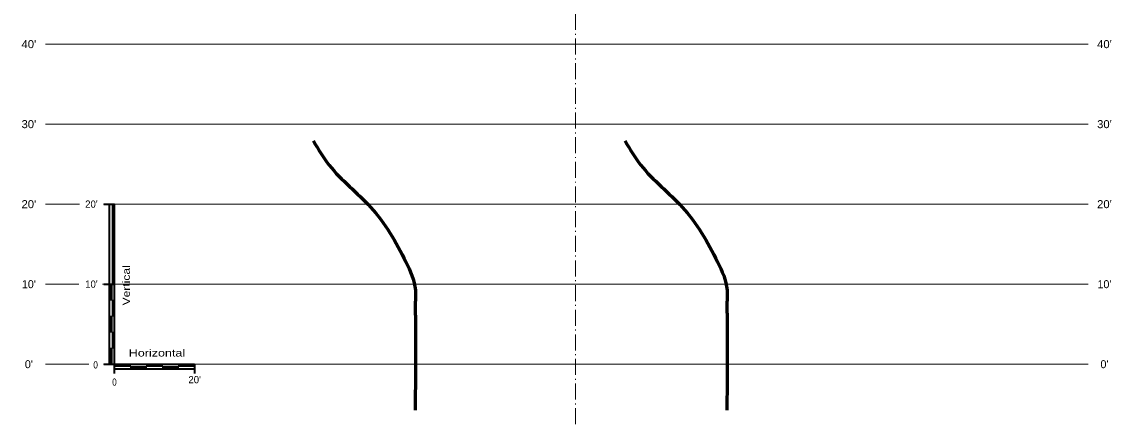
# Model space of a CAD drawing. Extents: x -582 to 653, y -817 to -3.
# Drawn here: x -65.9 to 70.2, y -611.9 to -561.3 of the extents above; entities that cross this region are included whole.
import ezdxf
from ezdxf.enums import TextEntityAlignment as Align

# ---------------------------------------------------------------- set-up
doc = ezdxf.new("R2010")
doc.units = 0
doc.header["$LTSCALE"] = 0.4
doc.linetypes.add('DOT_DASHED', pattern=[7.7, 5, -1.2, 0.3, -1.2])
for name, color, linetype, lineweight in [('27', 7, 'Continuous', 40), ('63', 7, 'Continuous', 35), ('7', 7, 'Continuous', 13)]:
    doc.layers.add(name, color=color, linetype=linetype, lineweight=lineweight)

msp = doc.modelspace()

# ---------------------------------------------------------------- linework, layer by layer
at = {"layer": '27', "lineweight": 60}
for points in [[(-29.4431, -576.2456), (-27.4801, -579.2507), (-22.2957, -584.5134), (-17.8965, -591.3427), (-16.7059, -594.8786), (-16.7059, -596.1329), (-16.7059, -598.1317), (-16.7247, -609.9069)], [(9.4859, -576.2456), (11.4489, -579.2507), (16.6333, -584.5134), (21.0325, -591.3427), (22.2231, -594.8786), (22.2231, -596.1329), (22.2231, -598.1317), (22.2043, -609.9069)]]:
    msp.add_spline(points, degree=3, dxfattribs=at)
at = {"layer": '63'}
for p, q in [((-55.6145, -584.1328), (-54.2879, -584.1328)), ((-54.8963, -604.1328), (-54.8963, -584.1328)), ((-54.2879, -605.2951), (-54.2879, -584.1328)), ((-55.6145, -594.1328), (-54.2879, -594.1328)), ((-55.6145, -604.1328), (-44.2879, -604.1328)), ((-54.2879, -604.7413), (-44.2879, -604.7413)), ((-44.2879, -604.1328), (-44.2879, -605.2951))]:
    msp.add_line(p, q, dxfattribs=at)
at = {"layer": '63', "lineweight": 13}
for p, q in [((-54.5897, -584.1328), (-54.5897, -604.1328)), ((-54.5646, -594.1328), (-54.5646, -584.1328)), ((-54.5392, -594.1328), (-54.5392, -584.1328)), ((-54.5138, -594.1328), (-54.5138, -584.1328)), ((-54.4884, -594.1328), (-54.4884, -584.1328)), ((-54.463, -594.1328), (-54.463, -584.1328)), ((-54.4376, -594.1328), (-54.4376, -584.1328)), ((-54.4122, -594.1328), (-54.4122, -584.1328)), ((-54.3868, -594.1328), (-54.3868, -584.1328)), ((-54.3614, -594.1328), (-54.3614, -584.1328)), ((-54.336, -594.1328), (-54.336, -584.1328)), ((-54.3106, -594.1328), (-54.3106, -584.1328)), ((-54.8694, -596.1328), (-54.8694, -594.1328)), ((-54.844, -596.1328), (-54.844, -594.1328)), ((-54.8186, -596.1328), (-54.8186, -594.1328)), ((-54.7932, -596.1328), (-54.7932, -594.1328)), ((-54.7678, -596.1328), (-54.7678, -594.1328)), ((-54.7424, -596.1328), (-54.7424, -594.1328)), ((-54.717, -596.1328), (-54.717, -594.1328)), ((-54.6916, -596.1328), (-54.6916, -594.1328)), ((-54.6662, -596.1328), (-54.6662, -594.1328)), ((-54.6408, -596.1328), (-54.6408, -594.1328)), ((-54.6154, -596.1328), (-54.6154, -594.1328)), ((-54.2879, -596.1328), (-54.8963, -596.1328)), ((-54.5674, -598.1328), (-54.5674, -596.1328)), ((-54.542, -598.1328), (-54.542, -596.1328)), ((-54.5166, -598.1328), (-54.5166, -596.1328)), ((-54.4912, -598.1328), (-54.4912, -596.1328)), ((-54.4658, -598.1328), (-54.4658, -596.1328)), ((-54.4404, -598.1328), (-54.4404, -596.1328)), ((-54.415, -598.1328), (-54.415, -596.1328)), ((-54.3896, -598.1328), (-54.3896, -596.1328)), ((-54.3642, -598.1328), (-54.3642, -596.1328)), ((-54.3388, -598.1328), (-54.3388, -596.1328)), ((-54.3134, -598.1328), (-54.3134, -596.1328)), ((-54.2879, -598.1328), (-54.8963, -598.1328)), ((-54.8694, -600.1328), (-54.8694, -598.1328)), ((-54.844, -600.1328), (-54.844, -598.1328)), ((-54.8186, -600.1328), (-54.8186, -598.1328)), ((-54.7932, -600.1328), (-54.7932, -598.1328)), ((-54.7678, -600.1328), (-54.7678, -598.1328)), ((-54.7424, -600.1328), (-54.7424, -598.1328)), ((-54.717, -600.1328), (-54.717, -598.1328)), ((-54.6916, -600.1328), (-54.6916, -598.1328)), ((-54.6662, -600.1328), (-54.6662, -598.1328)), ((-54.6408, -600.1328), (-54.6408, -598.1328)), ((-54.6154, -600.1328), (-54.6154, -598.1328)), ((-54.2879, -600.1328), (-54.8963, -600.1328)), ((-54.5674, -602.1328), (-54.5674, -600.1328)), ((-54.542, -602.1328), (-54.542, -600.1328)), ((-54.5166, -602.1328), (-54.5166, -600.1328)), ((-54.4912, -602.1328), (-54.4912, -600.1328)), ((-54.4658, -602.1328), (-54.4658, -600.1328)), ((-54.4404, -602.1328), (-54.4404, -600.1328)), ((-54.415, -602.1328), (-54.415, -600.1328)), ((-54.3896, -602.1328), (-54.3896, -600.1328)), ((-54.3642, -602.1328), (-54.3642, -600.1328)), ((-54.3388, -602.1328), (-54.3388, -600.1328)), ((-54.3134, -602.1328), (-54.3134, -600.1328)), ((-54.2879, -602.1328), (-54.8963, -602.1328)), ((-54.8694, -604.1328), (-54.8694, -602.1328)), ((-54.844, -604.1328), (-54.844, -602.1328)), ((-54.8186, -604.1328), (-54.8186, -602.1328)), ((-54.7932, -604.1328), (-54.7932, -602.1328)), ((-54.7678, -604.1328), (-54.7678, -602.1328)), ((-54.7424, -604.1328), (-54.7424, -602.1328)), ((-54.717, -604.1328), (-54.717, -602.1328)), ((-54.6916, -604.1328), (-54.6916, -602.1328)), ((-54.6662, -604.1328), (-54.6662, -602.1328)), ((-54.6408, -604.1328), (-54.6408, -602.1328)), ((-54.6154, -604.1328), (-54.6154, -602.1328)), ((-54.288, -604.1598), (-52.288, -604.1598)), ((-54.288, -604.1852), (-52.288, -604.1852)), ((-54.288, -604.2106), (-52.288, -604.2106)), ((-54.288, -604.236), (-52.288, -604.236)), ((-54.288, -604.2614), (-52.288, -604.2614)), ((-54.288, -604.2868), (-52.288, -604.2868)), ((-54.288, -604.3122), (-52.288, -604.3122)), ((-54.288, -604.3376), (-52.288, -604.3376)), ((-54.288, -604.363), (-52.288, -604.363)), ((-54.288, -604.3884), (-52.288, -604.3884)), ((-54.288, -604.4138), (-52.288, -604.4138)), ((-44.2879, -604.4394), (-54.2879, -604.4394)), ((-52.288, -604.4618), (-50.288, -604.4618)), ((-52.288, -604.4872), (-50.288, -604.4872)), ((-52.288, -604.5126), (-50.288, -604.5126)), ((-52.288, -604.538), (-50.288, -604.538)), ((-52.288, -604.5634), (-50.288, -604.5634)), ((-52.288, -604.5888), (-50.288, -604.5888)), ((-52.288, -604.6142), (-50.288, -604.6142)), ((-52.288, -604.6396), (-50.288, -604.6396)), ((-52.288, -604.665), (-50.288, -604.665)), ((-52.288, -604.6904), (-50.288, -604.6904)), ((-52.288, -604.7158), (-50.288, -604.7158)), ((-52.2879, -604.7413), (-52.2879, -604.1328)), ((-50.288, -604.1598), (-48.288, -604.1598)), ((-50.288, -604.1852), (-48.288, -604.1852)), ((-50.288, -604.2106), (-48.288, -604.2106)), ((-50.288, -604.236), (-48.288, -604.236)), ((-50.288, -604.2614), (-48.288, -604.2614)), ((-50.288, -604.2868), (-48.288, -604.2868)), ((-50.288, -604.3122), (-48.288, -604.3122)), ((-50.288, -604.3376), (-48.288, -604.3376)), ((-50.288, -604.363), (-48.288, -604.363)), ((-50.288, -604.3884), (-48.288, -604.3884)), ((-50.288, -604.4138), (-48.288, -604.4138)), ((-50.2879, -604.7413), (-50.2879, -604.1328)), ((-48.288, -604.4618), (-46.288, -604.4618)), ((-48.288, -604.4872), (-46.288, -604.4872)), ((-48.288, -604.5126), (-46.288, -604.5126)), ((-48.288, -604.538), (-46.288, -604.538)), ((-48.288, -604.5634), (-46.288, -604.5634)), ((-48.288, -604.5888), (-46.288, -604.5888)), ((-48.288, -604.6142), (-46.288, -604.6142)), ((-48.288, -604.6396), (-46.288, -604.6396)), ((-48.288, -604.665), (-46.288, -604.665)), ((-48.288, -604.6904), (-46.288, -604.6904)), ((-48.288, -604.7158), (-46.288, -604.7158)), ((-48.2879, -604.7413), (-48.2879, -604.1328)), ((-46.288, -604.1598), (-44.288, -604.1598)), ((-46.288, -604.1852), (-44.288, -604.1852)), ((-46.288, -604.2106), (-44.288, -604.2106)), ((-46.288, -604.236), (-44.288, -604.236)), ((-46.288, -604.2614), (-44.288, -604.2614)), ((-46.288, -604.2868), (-44.288, -604.2868)), ((-46.288, -604.3122), (-44.288, -604.3122)), ((-46.288, -604.3376), (-44.288, -604.3376)), ((-46.288, -604.363), (-44.288, -604.363)), ((-46.288, -604.3884), (-44.288, -604.3884)), ((-46.288, -604.4138), (-44.288, -604.4138)), ((-46.2879, -604.7413), (-46.2879, -604.1328))]:
    msp.add_line(p, q, dxfattribs=at)
at = {"layer": '7', "linetype": 'DOT_DASHED'}
msp.add_line((3.2787, -474.1328), (3.2787, -611.8952), dxfattribs=at)
msp.add_line((3.2787, -474.1328), (3.2787, -611.8952), dxfattribs=at)
at = {"layer": '7'}
for p, q in [((-62.9147, -564.1328), (28.379, -564.1328)), ((-23.9857, -564.1328), (67.308, -564.1328)), ((-62.9147, -574.1328), (28.379, -574.1328)), ((-23.9857, -574.1328), (67.308, -574.1328)), ((-62.9147, -584.1328), (-58.6601, -584.1328)), ((-55.6737, -584.1328), (28.379, -584.1328)), ((-16.7447, -584.1328), (67.308, -584.1328)), ((-62.9147, -594.1328), (-58.7505, -594.1328)), ((-55.7642, -594.1328), (28.379, -594.1328)), ((-53.5576, -594.1328), (-55.705, -594.1328)), ((-16.8351, -594.1328), (67.308, -594.1328)), ((-62.9147, -604.1328), (-57.4768, -604.1328)), ((-55.6737, -604.1328), (28.379, -604.1328)), ((-16.7447, -604.1328), (67.308, -604.1328))]:
    msp.add_line(p, q, dxfattribs=at)

# ---------------------------------------------------------------- texts
at = {"layer": '63'}
for s, height, width, p in [("40'", 1, 1.05, (-64.9762, -564.6436)), ("40'", 1, 1.05, (69.3612, -564.6435)), ("30'", 1, 1.05, (-64.9762, -574.6436)), ("30'", 1, 1.05, (69.3612, -574.6435)), ("20'", 1, 1.05, (-64.9762, -584.6436)), ("20'", 1, 1.05, (69.3612, -584.6435)), ('Horizontal', 0.9, 1.3, (-48.9765, -603.1826)), ('0', 0.9, 0.85, (-54.2882, -606.8296))]:
    msp.add_text(s, height=height, dxfattribs=dict(at, width=width)).set_placement(p, align=Align.CENTER)
for s, p in [("20'", (-56.3784, -584.5828)), ("10'", (-56.3784, -594.5828))]:
    msp.add_text(s, height=0.9, dxfattribs=at).set_placement(p, align=Align.RIGHT)
at = {"layer": '63', "width": 1.25}
msp.add_text('Vertical', height=0.9, rotation=90, dxfattribs=at).set_placement((-52.3639, -594.2861), align=Align.CENTER)
at = {"layer": '63'}
for s, height, p in [("10'", 1, (-64.9762, -594.6436)), ("10'", 1, (69.3612, -594.6435)), ("0'", 1, (-64.9763, -604.6436)), ("0'", 1, (69.3611, -604.6435)), ("20'", 0.9, (-44.2711, -606.5244))]:
    msp.add_text(s, height=height, dxfattribs=at).set_placement(p, align=Align.CENTER)
at = {"layer": '63', "width": 0.85}
msp.add_text('0', height=0.9, dxfattribs=at).set_placement((-56.3515, -604.6832), align=Align.RIGHT)

doc.saveas('drawing.dxf')
